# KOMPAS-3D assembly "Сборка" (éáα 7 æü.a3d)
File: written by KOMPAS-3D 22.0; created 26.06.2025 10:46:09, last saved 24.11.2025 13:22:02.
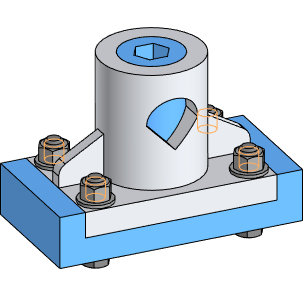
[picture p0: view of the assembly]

Document properties: Автор: Helen; Полное имя файла: C:\Для ноута\Инженерная графика\ППЭ 2025-2026\Варианты 1-38\Вариант 7 СБ\Вар 7 СБ\Вар 7 СБ.a3d

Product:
- Component [detail]: Сборка  | qty 4  | Масса: 0.008612; source file: Шайба 14.m3d
- Component [detail]: Сборка  | qty 4  | Масса: 0.02533; source file: Гайка М14.m3d
- Component [detail]: Болт М14x60 ГОСТ 15591-70  | qty 4  | Масса: 0.091885; source file: Болт М14x60 ГОСТ 15591-70.m3d
- Component [detail]: Основание  | designation Вариант 7  | qty 1  | Масса: 4.690027; source file: Основание вар 7.m3d
- Component [detail]: Nodes  | qty 1  | Масса: 3.986523; source file: Корпус вар 7.m3d
- Part/product: Сборка
    Масса: 9.179857

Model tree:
1. Массив по сетке:1  (with: Элемент выдавливания:4, Операция без истории:1, Элемент выдавливания:1)  (4 pattern instances)
     Шаг 1 = 120; Угол раствора = 90; Шаг 2 = 70

Referenced files in D:\MY\WORK\MPEI\ППЭ_2025-2026\Варианты\Вар 1 СБ\: Шайба 14.m3d, Гайка М14.m3d
Referenced files in C:\Для ноута\Инженерная графика\ППЭ 2025-2026\Варианты 1-38\Вариант 7 СБ\Вар 7 СБ\: Основание вар 7.m3d, Корпус вар 7.m3d, Болт М14x60 ГОСТ 15591-70.m3d
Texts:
  Сборка (1)
  Болт М14x60 ГОСТ 15591-70 (1)
  Вариант 7 Основание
